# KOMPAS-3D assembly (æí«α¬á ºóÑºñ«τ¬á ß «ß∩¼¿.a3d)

Referenced files in D:\МОДЕЛЬ ТАНКА Т90\ДЕТАЛИ\ХОДОВАЯ\звездочка\: ведущая звездочка.m3d, диск звездочки.m3d, ведущая звездочка1.m3d, ось звездочки.m3d, крышка звездочки наружняя.m3d
Referenced files in D:\МОДЕЛЬ ТАНКА Т90\ДЕТАЛИ\ХОДОВАЯ\Каток опорный с балансиром\: шпилька соеденения катков.m3d
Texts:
  Сборка звездочка  с осями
